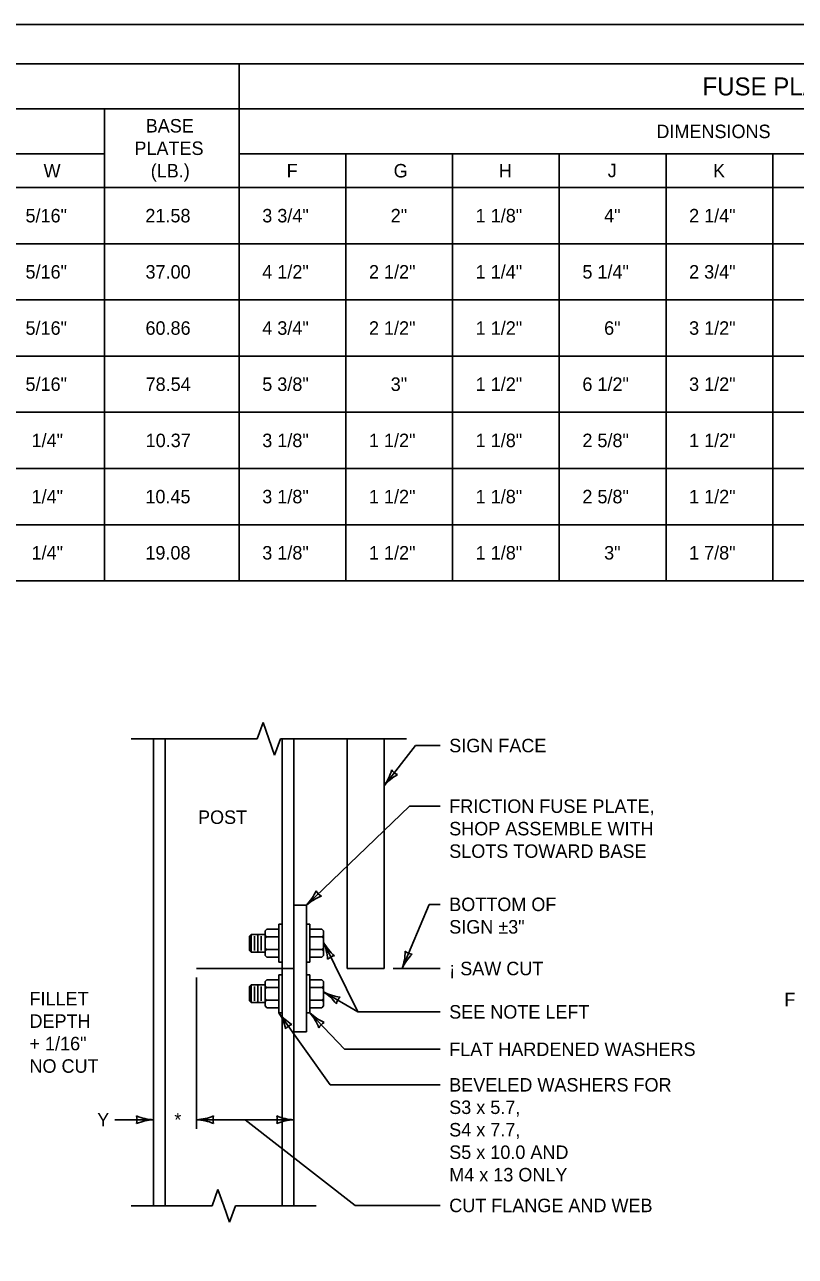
# Model space of a CAD drawing. Extents: x 49991.4 to 50021, y 49987.6 to 50011.4.
# Drawn here: x 50007.94 to 50011.38, y 49993.52 to 49999 of the extents above; entities that cross this region are included whole.
import ezdxf

# ---------------------------------------------------------------- set-up
doc = ezdxf.new("R2010")
doc.units = 0
for name, color, linetype in [('Level 1', 7, 'Continuous'), ('Level 2', 7, 'Continuous'), ('Level 3', 7, 'Continuous'), ('Level 6', 7, 'Continuous')]:
    doc.layers.add(name, color=color, linetype=linetype)

msp = doc.modelspace()

# ---------------------------------------------------------------- linework, layer by layer
at = {"layer": 'Level 1'}
for p, q in [((50008.5183, 49995.8214), (50008.5183, 49993.7433)), ((50008.57, 49995.8214), (50008.57, 49993.7433)), ((50009.0906, 49995.8214), (50009.0906, 49993.7433)), ((50009.1423, 49995.8214), (50009.1423, 49993.7433)), ((50009.3802, 49994.7994), (50009.3802, 49995.8214)), ((50009.5442, 49994.7994), (50009.5442, 49995.8214)), ((50009.1986, 49995.0807), (50009.1423, 49995.0807)), ((50009.1986, 49994.5182), (50009.1986, 49995.0807)), ((50009.0148, 49994.9664), (50009.0222, 49994.9739)), ((50009.0756, 49994.9739), (50009.0222, 49994.9739)), ((50009.0756, 49994.9964), (50009.0756, 49994.8276)), ((50009.0756, 49994.9964), (50009.0906, 49994.9964)), ((50009.2136, 49994.9964), (50009.1986, 49994.9964)), ((50009.2136, 49994.9964), (50009.2136, 49994.8276)), ((50009.2136, 49994.9739), (50009.267, 49994.9739)), ((50009.2744, 49994.9664), (50009.267, 49994.9739)), ((50008.9447, 49994.9439), (50008.9522, 49994.9514)), ((50008.9447, 49994.9439), (50008.9447, 49994.8801)), ((50008.9522, 49994.9514), (50009.0148, 49994.9514)), ((50008.9522, 49994.9514), (50008.9522, 49994.8726)), ((50008.9672, 49994.9439), (50008.9672, 49994.8801)), ((50008.9822, 49994.9514), (50008.9822, 49994.8726)), ((50008.9972, 49994.9439), (50008.9972, 49994.8801)), ((50009.0148, 49994.9664), (50009.0148, 49994.8576)), ((50009.0148, 49994.9476), (50009.0222, 49994.9401)), ((50009.0148, 49994.9326), (50009.0222, 49994.9401)), ((50009.0756, 49994.9401), (50009.0222, 49994.9401)), ((50009.2136, 49994.9401), (50009.267, 49994.9401)), ((50009.2744, 49994.9476), (50009.267, 49994.9401)), ((50009.2744, 49994.9326), (50009.267, 49994.9401)), ((50009.2744, 49994.9664), (50009.2744, 49994.8576)), ((50008.9447, 49994.8801), (50008.9522, 49994.8726)), ((50009.0148, 49994.8726), (50008.9522, 49994.8726)), ((50009.0148, 49994.8914), (50009.0222, 49994.8839)), ((50009.0148, 49994.8764), (50009.0222, 49994.8839)), ((50009.0756, 49994.8839), (50009.0222, 49994.8839)), ((50009.2136, 49994.8839), (50009.267, 49994.8839)), ((50009.2744, 49994.8914), (50009.267, 49994.8839)), ((50009.2744, 49994.8764), (50009.267, 49994.8839)), ((50009.0148, 49994.8576), (50009.0222, 49994.8501)), ((50009.0222, 49994.8501), (50009.0756, 49994.8501)), ((50009.0756, 49994.8276), (50009.0906, 49994.8276)), ((50009.2136, 49994.8276), (50009.1986, 49994.8276)), ((50009.267, 49994.8501), (50009.2136, 49994.8501)), ((50009.2744, 49994.8576), (50009.267, 49994.8501)), ((50009.1423, 49994.7994), (50008.7093, 49994.7994)), ((50009.0756, 49994.7714), (50009.0756, 49994.6026)), ((50009.0756, 49994.7714), (50009.0906, 49994.7714)), ((50009.2136, 49994.7714), (50009.1986, 49994.7714)), ((50009.2136, 49994.7714), (50009.2136, 49994.6026)), ((50009.3802, 49994.7994), (50009.5442, 49994.7994)), ((50008.9447, 49994.7188), (50008.9522, 49994.7264)), ((50008.9447, 49994.7188), (50008.9447, 49994.6551)), ((50008.9522, 49994.7264), (50009.0148, 49994.7264)), ((50008.9522, 49994.7264), (50008.9522, 49994.6476)), ((50008.9672, 49994.7188), (50008.9672, 49994.6551)), ((50008.9822, 49994.7264), (50008.9822, 49994.6476)), ((50008.9972, 49994.7188), (50008.9972, 49994.6551)), ((50009.0148, 49994.7414), (50009.0222, 49994.7488)), ((50009.0148, 49994.7414), (50009.0148, 49994.6326)), ((50009.0148, 49994.7226), (50009.0222, 49994.7151)), ((50009.0148, 49994.7076), (50009.0222, 49994.7151)), ((50009.0756, 49994.7488), (50009.0222, 49994.7488)), ((50009.0756, 49994.7151), (50009.0222, 49994.7151)), ((50009.2136, 49994.7488), (50009.267, 49994.7488)), ((50009.2136, 49994.7151), (50009.267, 49994.7151)), ((50009.2744, 49994.7414), (50009.267, 49994.7488)), ((50009.2744, 49994.7226), (50009.267, 49994.7151)), ((50009.2744, 49994.7076), (50009.267, 49994.7151)), ((50009.2744, 49994.7414), (50009.2744, 49994.6326)), ((50008.9447, 49994.6551), (50008.9522, 49994.6476)), ((50009.0148, 49994.6476), (50008.9522, 49994.6476)), ((50009.0148, 49994.6664), (50009.0222, 49994.6588)), ((50009.0148, 49994.6514), (50009.0222, 49994.6588)), ((50009.0756, 49994.6588), (50009.0222, 49994.6588)), ((50009.2136, 49994.6588), (50009.267, 49994.6588)), ((50009.2744, 49994.6664), (50009.267, 49994.6588)), ((50009.2744, 49994.6514), (50009.267, 49994.6588)), ((50009.0148, 49994.6326), (50009.0222, 49994.6251)), ((50009.0222, 49994.6251), (50009.0756, 49994.6251)), ((50009.0756, 49994.6026), (50009.0906, 49994.6026)), ((50009.2136, 49994.6026), (50009.1986, 49994.6026)), ((50009.267, 49994.6251), (50009.2136, 49994.6251)), ((50009.2744, 49994.6326), (50009.267, 49994.6251)), ((50009.1986, 49994.5182), (50009.1423, 49994.5182))]:
    msp.add_line(p, q, dxfattribs=at)
msp.add_lwpolyline([(49999.3835, 49998.9992), (50016.7501, 49998.9992), (50016.7501, 49987.7988), (49999.3835, 49987.7988)], close=True, dxfattribs=at)
at = {"layer": 'Level 2'}
for p, q in [((50002.7742, 49998.8242), (50016.4992, 49998.8242)), ((50008.8992, 49996.5242), (50008.8992, 49998.8242)), ((50002.7742, 49998.6242), (50016.4992, 49998.6242)), ((50008.2992, 49996.5242), (50008.2992, 49998.6242)), ((50004.9742, 49998.4242), (50008.2992, 49998.4242)), ((50008.2992, 49996.5242), (50008.2992, 49998.4242)), ((50008.8992, 49998.4242), (50013.1742, 49998.4242)), ((50009.3742, 49996.5242), (50009.3742, 49998.4242)), ((50009.8492, 49996.5242), (50009.8492, 49998.4242)), ((50010.3242, 49996.5242), (50010.3242, 49998.4242)), ((50010.7992, 49996.5242), (50010.7992, 49998.4242)), ((50011.2742, 49996.5242), (50011.2742, 49998.4242)), ((50002.7742, 49998.2742), (50016.4992, 49998.2742)), ((50004.9742, 49998.0242), (50016.4992, 49998.0242)), ((50002.7742, 49997.7742), (50016.4992, 49997.7742)), ((50004.9742, 49997.5242), (50016.4992, 49997.5242)), ((50002.7742, 49997.2742), (50016.4992, 49997.2742)), ((50004.9742, 49997.0242), (50016.4992, 49997.0242)), ((50002.7742, 49996.7742), (50016.4992, 49996.7742)), ((50002.7742, 49996.5242), (50016.4992, 49996.5242))]:
    msp.add_line(p, q, dxfattribs=at)
at = {"layer": 'Level 3'}
for p, q in [((50009.5442, 49995.6128), (50009.6842, 49995.7914)), ((50009.6842, 49995.7914), (50009.7942, 49995.7914)), ((50009.1986, 49995.0807), (50009.6571, 49995.5217)), ((50009.6571, 49995.5217), (50009.7942, 49995.5217)), ((50009.6242, 49994.7994), (50009.7442, 49995.0849)), ((50009.7442, 49995.0849), (50009.7942, 49995.0849)), ((50009.2744, 49994.9163), (50009.4273, 49994.6063)), ((50008.7093, 49994.7594), (50008.7093, 49994.0866)), ((50009.5842, 49994.7994), (50009.7942, 49994.7994)), ((50009.4273, 49994.6063), (50009.2744, 49994.6952)), ((50009.0756, 49994.6026), (50009.3037, 49994.282)), ((50009.2136, 49994.6026), (50009.3684, 49994.44)), ((50009.4273, 49994.6063), (50009.7942, 49994.6063)), ((50009.3684, 49994.44), (50009.7942, 49994.44)), ((50009.7942, 49994.282), (50009.3037, 49994.282)), ((50008.3449, 49994.1266), (50008.5183, 49994.1266)), ((50008.7093, 49994.1266), (50009.1423, 49994.1266)), ((50008.9258, 49994.1266), (50009.4149, 49993.7452)), ((50009.4149, 49993.7452), (50009.7942, 49993.7452))]:
    msp.add_line(p, q, dxfattribs=at)
for centre, radius, start, end in [((50009.354, 49995.7473), 0.233, 324.7353, 343.9852), ((50009.6233, 49995.7137), 0.0548, 214.0468, 249.7692), ((50009.7134, 49995.4686), 0.2223, 119.364, 139.5475), ((50009.029, 49995.2405), 0.233, 316.7127, 335.9626), ((50009.291, 49995.1696), 0.0548, 206.0243, 241.7466), ((50009.346, 49994.9143), 0.2223, 111.3414, 131.525), ((50009.0711, 49994.8263), 0.2223, 3.7097, 23.8932), ((50009.478, 49995.0295), 0.233, 209.081, 228.3309), ((50009.4052, 49994.879), 0.233, 340.0296, 359.2794), ((50009.8254, 49994.7049), 0.2223, 134.6583, 154.8418), ((50009.6739, 49994.9176), 0.0548, 229.3411, 265.0634), ((50009.3311, 49994.8013), 0.0548, 98.3925, 134.1149), ((50009.1548, 49994.5078), 0.2223, 37.2812, 57.4647), ((50009.3814, 49994.9022), 0.233, 242.6525, 261.9023), ((50009.3852, 49994.6308), 0.0548, 131.964, 167.6864), ((50008.8893, 49994.4813), 0.2223, 12.8864, 33.0699), ((50009.2586, 49994.7469), 0.233, 218.2577, 237.5075), ((50009.0464, 49994.4561), 0.2223, 21.0483, 41.2318), ((50009.3742, 49994.7714), 0.233, 226.4196, 245.6694), ((50009.1499, 49994.4981), 0.0548, 107.5692, 143.2915), ((50009.302, 49994.5097), 0.0548, 115.7311, 151.4534), ((50008.5275, 49994.3487), 0.2223, 247.456, 267.6395), ((50008.3901, 49994.1266), 0.0548, 342.1388, 17.8612), ((50008.5298, 49993.8939), 0.233, 92.8273, 112.0772), ((50008.6978, 49994.3593), 0.233, 272.8273, 292.0772), ((50008.7001, 49993.9045), 0.2223, 67.456, 87.6395), ((50008.8375, 49994.1266), 0.0548, 162.1388, 197.8612), ((50009.1515, 49994.3487), 0.2223, 247.456, 267.6395), ((50009.0141, 49994.1266), 0.0548, 342.1388, 17.8612), ((50009.1538, 49993.8939), 0.233, 92.8273, 112.0772)]:
    msp.add_arc(centre, radius, start, end, dxfattribs=at)
at = {"layer": 'Level 6'}
for p, q in [((50009.0053, 49995.8945), (50008.9794, 49995.8214)), ((50009.0053, 49995.8945), (50009.0312, 49995.8214)), ((50008.4183, 49995.8214), (50008.9794, 49995.8214)), ((50009.0312, 49995.8214), (50009.0571, 49995.7483)), ((50009.083, 49995.8214), (50009.0571, 49995.7483)), ((50009.083, 49995.8214), (50009.6442, 49995.8214)), ((50008.8044, 49993.8164), (50008.7785, 49993.7433)), ((50008.8044, 49993.8164), (50008.8303, 49993.7433)), ((50008.4183, 49993.7433), (50008.7785, 49993.7433)), ((50008.8303, 49993.7433), (50008.8562, 49993.6702)), ((50008.8821, 49993.7433), (50008.8562, 49993.6702)), ((50008.8821, 49993.7433), (50009.2423, 49993.7433))]:
    msp.add_line(p, q, dxfattribs=at)

# ---------------------------------------------------------------- texts
at = {"layer": 'Level 2'}
for s, height, p in [('FUSE PLATE DATA', 0.08, (50010.9616, 49998.6842)), ('BASE', 0.06, (50008.4831, 49998.5192)), ('DIMENSIONS', 0.06, (50010.7564, 49998.4942)), ('PLATES', 0.06, (50008.4328, 49998.4192)), ('W', 0.06, (50008.0285, 49998.3192)), ('(LB.)', 0.06, (50008.5054, 49998.3192)), ('F', 0.06, (50009.1106, 49998.3192)), ('G', 0.06, (50009.5869, 49998.3192)), ('H', 0.06, (50010.0547, 49998.3192)), ('J', 0.06, (50010.5399, 49998.3204)), ('K', 0.06, (50011.0086, 49998.3192)), ('5/16"', 0.06, (50007.948, 49998.1192)), ('21.58', 0.06, (50008.4816, 49998.1192)), ('3 3/4"', 0.06, (50009.002, 49998.1192)), ('2"', 0.06, (50009.5737, 49998.1192)), ('1 1/8"', 0.06, (50009.952, 49998.1192)), ('4"', 0.06, (50010.5237, 49998.1192)), ('2 1/4"', 0.06, (50010.902, 49998.1192)), ('5/16"', 0.06, (50007.948, 49997.8692)), ('37.00', 0.06, (50008.4822, 49997.8692)), ('4 1/2"', 0.06, (50009.002, 49997.8692)), ('2 1/2"', 0.06, (50009.477, 49997.8692)), ('1 1/4"', 0.06, (50009.952, 49997.8692)), ('5 1/4"', 0.06, (50010.427, 49997.8692)), ('2 3/4"', 0.06, (50010.902, 49997.8692)), ('5/16"', 0.06, (50007.948, 49997.6192)), ('60.86', 0.06, (50008.4821, 49997.6192)), ('4 3/4"', 0.06, (50009.002, 49997.6192)), ('2 1/2"', 0.06, (50009.477, 49997.6192)), ('1 1/2"', 0.06, (50009.952, 49997.6192)), ('6"', 0.06, (50010.5237, 49997.6192)), ('3 1/2"', 0.06, (50010.902, 49997.6192)), ('5/16"', 0.06, (50007.948, 49997.3692)), ('78.54', 0.06, (50008.4826, 49997.3692)), ('5 3/8"', 0.06, (50009.002, 49997.3692)), ('3"', 0.06, (50009.5737, 49997.3692)), ('1 1/2"', 0.06, (50009.952, 49997.3692)), ('6 1/2"', 0.06, (50010.427, 49997.3692)), ('3 1/2"', 0.06, (50010.902, 49997.3692)), ('1/4"', 0.06, (50007.975, 49997.1192)), ('10.37', 0.06, (50008.4828, 49997.1192)), ('3 1/8"', 0.06, (50009.002, 49997.1192)), ('1 1/2"', 0.06, (50009.477, 49997.1192)), ('1 1/8"', 0.06, (50009.952, 49997.1192)), ('2 5/8"', 0.06, (50010.427, 49997.1192)), ('1 1/2"', 0.06, (50010.902, 49997.1192)), ('1/4"', 0.06, (50007.975, 49996.8692)), ('10.45', 0.06, (50008.4817, 49996.8692)), ('3 1/8"', 0.06, (50009.002, 49996.8692)), ('1 1/2"', 0.06, (50009.477, 49996.8692)), ('1 1/8"', 0.06, (50009.952, 49996.8692)), ('2 5/8"', 0.06, (50010.427, 49996.8692)), ('1 1/2"', 0.06, (50010.902, 49996.8692)), ('1/4"', 0.06, (50007.975, 49996.6192)), ('19.08', 0.06, (50008.4816, 49996.6192)), ('3 1/8"', 0.06, (50009.002, 49996.6192)), ('1 1/2"', 0.06, (50009.477, 49996.6192)), ('1 1/8"', 0.06, (50009.952, 49996.6192)), ('3"', 0.06, (50010.5237, 49996.6192)), ('1 7/8"', 0.06, (50010.902, 49996.6192)), ('SIGN FACE', 0.06, (50009.8342, 49995.7614)), ('FRICTION FUSE PLATE,', 0.06, (50009.8342, 49995.4917)), ('POST', 0.06, (50008.716, 49995.4427)), ('SHOP ASSEMBLE WITH', 0.06, (50009.8342, 49995.3917)), ('SLOTS TOWARD BASE', 0.06, (50009.8342, 49995.2917)), ('BOTTOM OF', 0.06, (50009.8342, 49995.0549)), ('SIGN ±3"', 0.06, (50009.8342, 49994.9549)), ('¡ SAW CUT', 0.06, (50009.8342, 49994.7694)), ('FILLET', 0.06, (50007.9657, 49994.6354)), ('F', 0.06, (50011.326, 49994.6315)), ('DEPTH', 0.06, (50007.9657, 49994.5354)), ('SEE NOTE LEFT', 0.06, (50009.8342, 49994.5763)), ('+ 1/16"', 0.06, (50007.9657, 49994.4354)), ('FLAT HARDENED WASHERS', 0.06, (50009.8342, 49994.41)), ('NO CUT', 0.06, (50007.9657, 49994.3354)), ('BEVELED WASHERS FOR', 0.06, (50009.8342, 49994.252)), ('S3 x 5.7,', 0.06, (50009.8342, 49994.152)), ('Y', 0.06, (50008.2671, 49994.0966)), ('*', 0.06, (50008.6104, 49994.0966)), ('S4 x 7.7,', 0.06, (50009.8342, 49994.052)), ('S5 x 10.0 AND', 0.06, (50009.8342, 49993.952)), ('M4 x 13 ONLY', 0.06, (50009.8342, 49993.852)), ('CUT FLANGE AND WEB', 0.06, (50009.8342, 49993.7152))]:
    msp.add_text(s, height=height, dxfattribs=at).set_placement(p)

doc.saveas('drawing.dxf')
